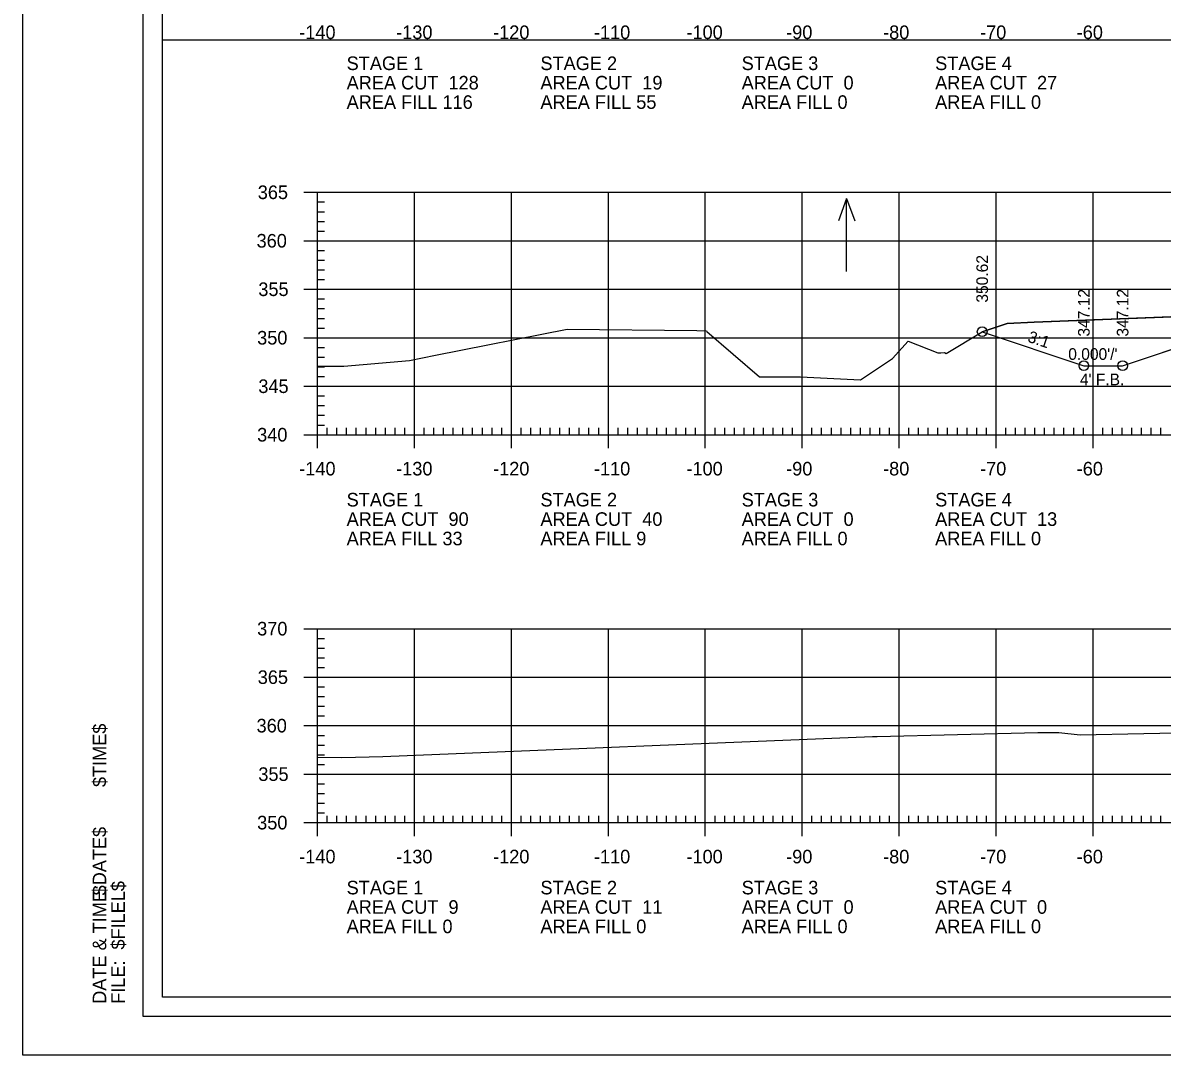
# Model space of a CAD drawing. Extents: x 1368910 to 1369601, y 380116 to 380950.
# Drawn here: x 1369267.2 to 1369384.7, y 380310.4 to 380416.9 of the extents above; entities that cross this region are included whole.
import ezdxf

# ---------------------------------------------------------------- set-up
doc = ezdxf.new("R2010")
doc.units = 0
for name, color, linetype in [('_STAGE 1 CUT', 7, 'Continuous'), ('R_Axis', 7, 'Continuous'), ('R_Axis Annot', 7, 'Continuous'), ('R_Border', 7, 'Continuous'), ('R_Border Notes', 7, 'Continuous'), ('R_Exist Surface', 7, 'Continuous'), ('R_Fin Surface', 7, 'Continuous'), ('R_Grid', 7, 'Continuous'), ('R_No Plot', 7, 'Continuous'), ('R_Water Annot', 7, 'Continuous'), ('R_Xsect Elev', 7, 'Continuous'), ('R_Xsect Slope', 7, 'Continuous')]:
    doc.layers.add(name, color=color, linetype=linetype)

msp = doc.modelspace()

# ---------------------------------------------------------------- linework, layer by layer
at = {"layer": '_STAGE 1 CUT'}
msp.add_line((1369366.16, 380385.04), (1369376.64, 380381.54), dxfattribs=at)
for points in [[(1369397.06, 380387.02), (1369371.53, 380386.03), (1369368.73, 380385.9), (1369366.16, 380385.04)], [(1369376.64, 380381.54), (1369380.64, 380381.54), (1369397.06, 380387.02)], [(1369366.16, 380385.04), (1369366.16, 380385.04)]]:
    msp.add_lwpolyline(points, dxfattribs=at)
at = {"layer": 'R_Axis'}
for p, q in [((1369296.19, 380399.42), (1369298.99, 380399.42)), ((1369297.59, 380374.42), (1369297.59, 380399.42)), ((1369297.59, 380398.42), (1369298.29, 380398.42)), ((1369297.59, 380397.42), (1369298.29, 380397.42)), ((1369297.59, 380396.42), (1369298.29, 380396.42)), ((1369297.59, 380395.42), (1369298.29, 380395.42)), ((1369296.19, 380394.42), (1369298.99, 380394.42)), ((1369297.59, 380393.42), (1369298.29, 380393.42)), ((1369297.59, 380392.42), (1369298.29, 380392.42)), ((1369297.59, 380391.42), (1369298.29, 380391.42)), ((1369297.59, 380390.42), (1369298.29, 380390.42)), ((1369296.19, 380389.42), (1369298.99, 380389.42)), ((1369297.59, 380388.42), (1369298.29, 380388.42)), ((1369297.59, 380387.42), (1369298.29, 380387.42)), ((1369297.59, 380386.42), (1369298.29, 380386.42)), ((1369297.59, 380385.42), (1369298.29, 380385.42)), ((1369296.19, 380384.42), (1369298.99, 380384.42)), ((1369297.59, 380383.42), (1369298.29, 380383.42)), ((1369297.59, 380382.42), (1369298.29, 380382.42)), ((1369297.59, 380381.42), (1369298.29, 380381.42)), ((1369297.59, 380380.42), (1369298.29, 380380.42)), ((1369296.19, 380379.42), (1369298.99, 380379.42)), ((1369297.59, 380378.42), (1369298.29, 380378.42)), ((1369297.59, 380377.42), (1369298.29, 380377.42)), ((1369297.59, 380376.42), (1369298.29, 380376.42)), ((1369297.59, 380373.02), (1369297.59, 380375.82)), ((1369307.59, 380373.02), (1369307.59, 380375.82)), ((1369317.59, 380373.02), (1369317.59, 380375.82)), ((1369327.59, 380373.02), (1369327.59, 380375.82)), ((1369337.59, 380373.02), (1369337.59, 380375.82)), ((1369347.59, 380373.02), (1369347.59, 380375.82)), ((1369357.59, 380373.02), (1369357.59, 380375.82)), ((1369367.59, 380373.02), (1369367.59, 380375.82)), ((1369377.59, 380373.02), (1369377.59, 380375.82)), ((1369297.59, 380375.42), (1369298.29, 380375.42)), ((1369298.59, 380374.42), (1369298.59, 380375.12)), ((1369299.59, 380374.42), (1369299.59, 380375.12)), ((1369300.59, 380374.42), (1369300.59, 380375.12)), ((1369301.59, 380374.42), (1369301.59, 380375.12)), ((1369302.59, 380374.42), (1369302.59, 380375.12)), ((1369303.59, 380374.42), (1369303.59, 380375.12)), ((1369304.59, 380374.42), (1369304.59, 380375.12)), ((1369305.59, 380374.42), (1369305.59, 380375.12)), ((1369306.59, 380374.42), (1369306.59, 380375.12)), ((1369308.59, 380374.42), (1369308.59, 380375.12)), ((1369309.59, 380374.42), (1369309.59, 380375.12)), ((1369310.59, 380374.42), (1369310.59, 380375.12)), ((1369311.59, 380374.42), (1369311.59, 380375.12)), ((1369312.59, 380374.42), (1369312.59, 380375.12)), ((1369313.59, 380374.42), (1369313.59, 380375.12)), ((1369314.59, 380374.42), (1369314.59, 380375.12)), ((1369315.59, 380374.42), (1369315.59, 380375.12)), ((1369316.59, 380374.42), (1369316.59, 380375.12)), ((1369318.59, 380374.42), (1369318.59, 380375.12)), ((1369319.59, 380374.42), (1369319.59, 380375.12)), ((1369320.59, 380374.42), (1369320.59, 380375.12)), ((1369321.59, 380374.42), (1369321.59, 380375.12)), ((1369322.59, 380374.42), (1369322.59, 380375.12)), ((1369323.59, 380374.42), (1369323.59, 380375.12)), ((1369324.59, 380374.42), (1369324.59, 380375.12)), ((1369325.59, 380374.42), (1369325.59, 380375.12)), ((1369326.59, 380374.42), (1369326.59, 380375.12)), ((1369328.59, 380374.42), (1369328.59, 380375.12)), ((1369329.59, 380374.42), (1369329.59, 380375.12)), ((1369330.59, 380374.42), (1369330.59, 380375.12)), ((1369331.59, 380374.42), (1369331.59, 380375.12)), ((1369332.59, 380374.42), (1369332.59, 380375.12)), ((1369333.59, 380374.42), (1369333.59, 380375.12)), ((1369334.59, 380374.42), (1369334.59, 380375.12)), ((1369335.59, 380374.42), (1369335.59, 380375.12)), ((1369336.59, 380374.42), (1369336.59, 380375.12)), ((1369338.59, 380374.42), (1369338.59, 380375.12)), ((1369339.59, 380374.42), (1369339.59, 380375.12)), ((1369340.59, 380374.42), (1369340.59, 380375.12)), ((1369341.59, 380374.42), (1369341.59, 380375.12)), ((1369342.59, 380374.42), (1369342.59, 380375.12)), ((1369343.59, 380374.42), (1369343.59, 380375.12)), ((1369344.59, 380374.42), (1369344.59, 380375.12)), ((1369345.59, 380374.42), (1369345.59, 380375.12)), ((1369346.59, 380374.42), (1369346.59, 380375.12)), ((1369348.59, 380374.42), (1369348.59, 380375.12)), ((1369349.59, 380374.42), (1369349.59, 380375.12)), ((1369350.59, 380374.42), (1369350.59, 380375.12)), ((1369351.59, 380374.42), (1369351.59, 380375.12)), ((1369352.59, 380374.42), (1369352.59, 380375.12)), ((1369353.59, 380374.42), (1369353.59, 380375.12)), ((1369354.59, 380374.42), (1369354.59, 380375.12)), ((1369355.59, 380374.42), (1369355.59, 380375.12)), ((1369356.59, 380374.42), (1369356.59, 380375.12)), ((1369358.59, 380374.42), (1369358.59, 380375.12)), ((1369359.59, 380374.42), (1369359.59, 380375.12)), ((1369360.59, 380374.42), (1369360.59, 380375.12)), ((1369361.59, 380374.42), (1369361.59, 380375.12)), ((1369362.59, 380374.42), (1369362.59, 380375.12)), ((1369363.59, 380374.42), (1369363.59, 380375.12)), ((1369364.59, 380374.42), (1369364.59, 380375.12)), ((1369365.59, 380374.42), (1369365.59, 380375.12)), ((1369366.59, 380374.42), (1369366.59, 380375.12)), ((1369368.59, 380374.42), (1369368.59, 380375.12)), ((1369369.59, 380374.42), (1369369.59, 380375.12)), ((1369370.59, 380374.42), (1369370.59, 380375.12)), ((1369371.59, 380374.42), (1369371.59, 380375.12)), ((1369372.59, 380374.42), (1369372.59, 380375.12)), ((1369373.59, 380374.42), (1369373.59, 380375.12)), ((1369374.59, 380374.42), (1369374.59, 380375.12)), ((1369375.59, 380374.42), (1369375.59, 380375.12)), ((1369376.59, 380374.42), (1369376.59, 380375.12)), ((1369378.59, 380374.42), (1369378.59, 380375.12)), ((1369379.59, 380374.42), (1369379.59, 380375.12)), ((1369380.59, 380374.42), (1369380.59, 380375.12)), ((1369381.59, 380374.42), (1369381.59, 380375.12)), ((1369382.59, 380374.42), (1369382.59, 380375.12)), ((1369383.59, 380374.42), (1369383.59, 380375.12)), ((1369384.59, 380374.42), (1369384.59, 380375.12)), ((1369296.19, 380374.42), (1369298.99, 380374.42)), ((1369297.59, 380374.42), (1369577.59, 380374.42)), ((1369296.19, 380354.42), (1369298.99, 380354.42)), ((1369297.59, 380334.42), (1369297.59, 380354.42)), ((1369297.59, 380353.42), (1369298.29, 380353.42)), ((1369297.59, 380352.42), (1369298.29, 380352.42)), ((1369297.59, 380351.42), (1369298.29, 380351.42)), ((1369297.59, 380350.42), (1369298.29, 380350.42)), ((1369296.19, 380349.42), (1369298.99, 380349.42)), ((1369297.59, 380348.42), (1369298.29, 380348.42)), ((1369297.59, 380347.42), (1369298.29, 380347.42)), ((1369297.59, 380346.42), (1369298.29, 380346.42)), ((1369297.59, 380345.42), (1369298.29, 380345.42)), ((1369296.19, 380344.42), (1369298.99, 380344.42)), ((1369297.59, 380343.42), (1369298.29, 380343.42)), ((1369297.59, 380342.42), (1369298.29, 380342.42)), ((1369297.59, 380341.42), (1369298.29, 380341.42)), ((1369297.59, 380340.42), (1369298.29, 380340.42)), ((1369296.19, 380339.42), (1369298.99, 380339.42)), ((1369297.59, 380338.42), (1369298.29, 380338.42)), ((1369297.59, 380337.42), (1369298.29, 380337.42)), ((1369297.59, 380336.42), (1369298.29, 380336.42)), ((1369297.59, 380333.02), (1369297.59, 380335.82)), ((1369307.59, 380333.02), (1369307.59, 380335.82)), ((1369317.59, 380333.02), (1369317.59, 380335.82)), ((1369327.59, 380333.02), (1369327.59, 380335.82)), ((1369337.59, 380333.02), (1369337.59, 380335.82)), ((1369347.59, 380333.02), (1369347.59, 380335.82)), ((1369357.59, 380333.02), (1369357.59, 380335.82)), ((1369367.59, 380333.02), (1369367.59, 380335.82)), ((1369377.59, 380333.02), (1369377.59, 380335.82)), ((1369297.59, 380335.42), (1369298.29, 380335.42)), ((1369298.59, 380334.42), (1369298.59, 380335.12)), ((1369299.59, 380334.42), (1369299.59, 380335.12)), ((1369300.59, 380334.42), (1369300.59, 380335.12)), ((1369301.59, 380334.42), (1369301.59, 380335.12)), ((1369302.59, 380334.42), (1369302.59, 380335.12)), ((1369303.59, 380334.42), (1369303.59, 380335.12)), ((1369304.59, 380334.42), (1369304.59, 380335.12)), ((1369305.59, 380334.42), (1369305.59, 380335.12)), ((1369306.59, 380334.42), (1369306.59, 380335.12)), ((1369308.59, 380334.42), (1369308.59, 380335.12)), ((1369309.59, 380334.42), (1369309.59, 380335.12)), ((1369310.59, 380334.42), (1369310.59, 380335.12)), ((1369311.59, 380334.42), (1369311.59, 380335.12)), ((1369312.59, 380334.42), (1369312.59, 380335.12)), ((1369313.59, 380334.42), (1369313.59, 380335.12)), ((1369314.59, 380334.42), (1369314.59, 380335.12)), ((1369315.59, 380334.42), (1369315.59, 380335.12)), ((1369316.59, 380334.42), (1369316.59, 380335.12)), ((1369318.59, 380334.42), (1369318.59, 380335.12)), ((1369319.59, 380334.42), (1369319.59, 380335.12)), ((1369320.59, 380334.42), (1369320.59, 380335.12)), ((1369321.59, 380334.42), (1369321.59, 380335.12)), ((1369322.59, 380334.42), (1369322.59, 380335.12)), ((1369323.59, 380334.42), (1369323.59, 380335.12)), ((1369324.59, 380334.42), (1369324.59, 380335.12)), ((1369325.59, 380334.42), (1369325.59, 380335.12)), ((1369326.59, 380334.42), (1369326.59, 380335.12)), ((1369328.59, 380334.42), (1369328.59, 380335.12)), ((1369329.59, 380334.42), (1369329.59, 380335.12)), ((1369330.59, 380334.42), (1369330.59, 380335.12)), ((1369331.59, 380334.42), (1369331.59, 380335.12)), ((1369332.59, 380334.42), (1369332.59, 380335.12)), ((1369333.59, 380334.42), (1369333.59, 380335.12)), ((1369334.59, 380334.42), (1369334.59, 380335.12)), ((1369335.59, 380334.42), (1369335.59, 380335.12)), ((1369336.59, 380334.42), (1369336.59, 380335.12)), ((1369338.59, 380334.42), (1369338.59, 380335.12)), ((1369339.59, 380334.42), (1369339.59, 380335.12)), ((1369340.59, 380334.42), (1369340.59, 380335.12)), ((1369341.59, 380334.42), (1369341.59, 380335.12)), ((1369342.59, 380334.42), (1369342.59, 380335.12)), ((1369343.59, 380334.42), (1369343.59, 380335.12)), ((1369344.59, 380334.42), (1369344.59, 380335.12)), ((1369345.59, 380334.42), (1369345.59, 380335.12)), ((1369346.59, 380334.42), (1369346.59, 380335.12)), ((1369348.59, 380334.42), (1369348.59, 380335.12)), ((1369349.59, 380334.42), (1369349.59, 380335.12)), ((1369350.59, 380334.42), (1369350.59, 380335.12)), ((1369351.59, 380334.42), (1369351.59, 380335.12)), ((1369352.59, 380334.42), (1369352.59, 380335.12)), ((1369353.59, 380334.42), (1369353.59, 380335.12)), ((1369354.59, 380334.42), (1369354.59, 380335.12)), ((1369355.59, 380334.42), (1369355.59, 380335.12)), ((1369356.59, 380334.42), (1369356.59, 380335.12)), ((1369358.59, 380334.42), (1369358.59, 380335.12)), ((1369359.59, 380334.42), (1369359.59, 380335.12)), ((1369360.59, 380334.42), (1369360.59, 380335.12)), ((1369361.59, 380334.42), (1369361.59, 380335.12)), ((1369362.59, 380334.42), (1369362.59, 380335.12)), ((1369363.59, 380334.42), (1369363.59, 380335.12)), ((1369364.59, 380334.42), (1369364.59, 380335.12)), ((1369365.59, 380334.42), (1369365.59, 380335.12)), ((1369366.59, 380334.42), (1369366.59, 380335.12)), ((1369368.59, 380334.42), (1369368.59, 380335.12)), ((1369369.59, 380334.42), (1369369.59, 380335.12)), ((1369370.59, 380334.42), (1369370.59, 380335.12)), ((1369371.59, 380334.42), (1369371.59, 380335.12)), ((1369372.59, 380334.42), (1369372.59, 380335.12)), ((1369373.59, 380334.42), (1369373.59, 380335.12)), ((1369374.59, 380334.42), (1369374.59, 380335.12)), ((1369375.59, 380334.42), (1369375.59, 380335.12)), ((1369376.59, 380334.42), (1369376.59, 380335.12)), ((1369378.59, 380334.42), (1369378.59, 380335.12)), ((1369379.59, 380334.42), (1369379.59, 380335.12)), ((1369380.59, 380334.42), (1369380.59, 380335.12)), ((1369381.59, 380334.42), (1369381.59, 380335.12)), ((1369382.59, 380334.42), (1369382.59, 380335.12)), ((1369383.59, 380334.42), (1369383.59, 380335.12)), ((1369384.59, 380334.42), (1369384.59, 380335.12)), ((1369296.19, 380334.42), (1369298.99, 380334.42)), ((1369297.59, 380334.42), (1369577.59, 380334.42))]:
    msp.add_line(p, q, dxfattribs=at)
at = {"layer": 'R_Border'}
for p, q in [((1369279.59, 380314.42), (1369279.59, 380519.88)), ((1369279.59, 380314.42), (1369279.59, 380314.42)), ((1369595.77, 380314.42), (1369279.59, 380314.42))]:
    msp.add_line(p, q, dxfattribs=at)
at = {"layer": 'R_Exist Surface'}
for points in [[(1369297.59, 380381.5), (1369300.31, 380381.49), (1369307.07, 380382.09), (1369309.76, 380382.63), (1369323.33, 380385.31), (1369336.72, 380385.15), (1369337.72, 380385.14), (1369337.76, 380385.08), (1369343.17, 380380.4), (1369347.4, 380380.38), (1369353.59, 380380.09), (1369356.9, 380382.27), (1369358.52, 380384.05), (1369361.58, 380382.87), (1369361.87, 380382.86), (1369362.27, 380382.89), (1369362.45, 380382.81), (1369366.16, 380385.04), (1369368.73, 380385.9), (1369371.53, 380386.03), (1369397.24, 380387.02)], [(1369297.59, 380341.16), (1369300.09, 380341.12), (1369304.33, 380341.25), (1369354.84, 380343.3), (1369355.32, 380343.31), (1369371.88, 380343.7), (1369374.05, 380343.72), (1369376.27, 380343.48), (1369389.41, 380343.75)]]:
    msp.add_lwpolyline(points, dxfattribs=at)
at = {"layer": 'R_Fin Surface'}
msp.add_lwpolyline([(1369366.15, 380385.04), (1369376.64, 380381.54), (1369380.64, 380381.54), (1369404.59, 380389.53), (1369412.86, 380390.9), (1369418.59, 380391.86), (1369426.59, 380392.18), (1369437.59, 380392.4), (1369448.59, 380392.18), (1369456.59, 380391.86), (1369462.32, 380390.9), (1369470.59, 380389.53), (1369478.65, 380386.84), (1369482.65, 380386.84), (1369492.02, 380389.96)], dxfattribs=at)
at = {"layer": 'R_Grid'}
for p, q in [((1369297.59, 380399.42), (1369577.59, 380399.42)), ((1369297.59, 380374.42), (1369297.59, 380399.42)), ((1369307.59, 380374.42), (1369307.59, 380399.42)), ((1369317.59, 380374.42), (1369317.59, 380399.42)), ((1369327.59, 380374.42), (1369327.59, 380399.42)), ((1369337.59, 380374.42), (1369337.59, 380399.42)), ((1369347.59, 380374.42), (1369347.59, 380399.42)), ((1369357.59, 380374.42), (1369357.59, 380399.42)), ((1369367.59, 380374.42), (1369367.59, 380399.42)), ((1369377.59, 380374.42), (1369377.59, 380399.42)), ((1369297.59, 380394.42), (1369577.59, 380394.42)), ((1369297.59, 380389.42), (1369577.59, 380389.42)), ((1369297.59, 380384.42), (1369577.59, 380384.42)), ((1369297.59, 380379.42), (1369577.59, 380379.42)), ((1369297.59, 380374.42), (1369577.59, 380374.42)), ((1369297.59, 380354.42), (1369577.59, 380354.42)), ((1369297.59, 380334.42), (1369297.59, 380354.42)), ((1369307.59, 380334.42), (1369307.59, 380354.42)), ((1369317.59, 380334.42), (1369317.59, 380354.42)), ((1369327.59, 380334.42), (1369327.59, 380354.42)), ((1369337.59, 380334.42), (1369337.59, 380354.42)), ((1369347.59, 380334.42), (1369347.59, 380354.42)), ((1369357.59, 380334.42), (1369357.59, 380354.42)), ((1369367.59, 380334.42), (1369367.59, 380354.42)), ((1369377.59, 380334.42), (1369377.59, 380354.42)), ((1369297.59, 380349.42), (1369577.59, 380349.42)), ((1369297.59, 380344.42), (1369577.59, 380344.42)), ((1369297.59, 380339.42), (1369577.59, 380339.42)), ((1369297.59, 380334.42), (1369577.59, 380334.42))]:
    msp.add_line(p, q, dxfattribs=at)
at = {"layer": 'R_No Plot'}
for points in [[(1369267.18, 380523.78), (1369600.52, 380523.78), (1369600.52, 380310.44), (1369267.18, 380310.44)], [(1369281.59, 380517.88), (1369531.13, 380517.88), (1369531.13, 380508), (1369548.67, 380508), (1369572.77, 380508), (1369572.77, 380485.67), (1369593.77, 380485.67), (1369593.77, 380316.42), (1369281.59, 380316.42)], [(1369281.59, 380415.15), (1369593.77, 380415.15), (1369593.77, 380316.42), (1369281.59, 380316.42)]]:
    msp.add_lwpolyline(points, close=True, dxfattribs=at)
for centre in [(1369366.15, 380385.04), (1369376.64, 380381.54), (1369380.64, 380381.54)]:
    msp.add_circle(centre, 0.5, dxfattribs=at)
at = {"layer": 'R_Water Annot'}
for p, q in [((1369352.16, 380398.79), (1369351.32, 380396.48)), ((1369352.16, 380391.25), (1369352.16, 380398.79)), ((1369352.16, 380398.79), (1369353, 380396.48))]:
    msp.add_line(p, q, dxfattribs=at)

# ---------------------------------------------------------------- texts
at = {"layer": 'R_Axis Annot'}
for s, p in [('-140', (1369295.7, 380415.22)), ('-130', (1369305.7, 380415.22)), ('-120', (1369315.7, 380415.22)), ('-110', (1369326.1, 380415.22)), ('-100', (1369335.64, 380415.22)), ('-90', (1369345.93, 380415.22)), ('-80', (1369355.93, 380415.22)), ('-70', (1369365.93, 380415.22)), ('-60', (1369375.9, 380415.22)), ('STAGE 1', (1369300.59, 380412.02)), ('STAGE 2', (1369320.58, 380412.02)), ('STAGE 3', (1369341.34, 380412.02)), ('STAGE 4', (1369361.3, 380412.02)), ('AREA CUT  128', (1369300.59, 380410.02)), ('AREA CUT  19', (1369320.58, 380410.02)), ('AREA CUT  0', (1369341.34, 380410.02)), ('AREA CUT  27', (1369361.3, 380410.02)), ('AREA FILL 116', (1369300.59, 380408.02)), ('AREA FILL 55', (1369320.58, 380408.02)), ('AREA FILL 0', (1369341.34, 380408.02)), ('AREA FILL 0', (1369361.3, 380408.02)), ('365', (1369291.42, 380398.72)), ('360', (1369291.3, 380393.72)), ('355', (1369291.48, 380388.72)), ('350', (1369291.36, 380383.72)), ('345', (1369291.48, 380378.72)), ('340', (1369291.36, 380373.72)), ('-140', (1369295.7, 380370.22)), ('-130', (1369305.7, 380370.22)), ('-120', (1369315.7, 380370.22)), ('-110', (1369326.1, 380370.22)), ('-100', (1369335.64, 380370.22)), ('-90', (1369345.93, 380370.22)), ('-80', (1369355.93, 380370.22)), ('-70', (1369365.93, 380370.22)), ('-60', (1369375.9, 380370.22)), ('STAGE 1', (1369300.59, 380367.02)), ('STAGE 2', (1369320.58, 380367.02)), ('STAGE 3', (1369341.34, 380367.02)), ('STAGE 4', (1369361.3, 380367.02)), ('AREA CUT  90', (1369300.59, 380365.02)), ('AREA CUT  40', (1369320.58, 380365.02)), ('AREA CUT  0', (1369341.34, 380365.02)), ('AREA CUT  13', (1369361.3, 380365.02)), ('AREA FILL 33', (1369300.59, 380363.02)), ('AREA FILL 9', (1369320.58, 380363.02)), ('AREA FILL 0', (1369341.34, 380363.02)), ('AREA FILL 0', (1369361.3, 380363.02)), ('370', (1369291.36, 380353.72)), ('365', (1369291.42, 380348.72)), ('360', (1369291.3, 380343.72)), ('355', (1369291.48, 380338.72)), ('350', (1369291.36, 380333.72)), ('-140', (1369295.7, 380330.22)), ('-130', (1369305.7, 380330.22)), ('-120', (1369315.7, 380330.22)), ('-110', (1369326.1, 380330.22)), ('-100', (1369335.64, 380330.22)), ('-90', (1369345.93, 380330.22)), ('-80', (1369355.93, 380330.22)), ('-70', (1369365.93, 380330.22)), ('-60', (1369375.9, 380330.22)), ('STAGE 1', (1369300.59, 380327.02)), ('STAGE 2', (1369320.58, 380327.02)), ('STAGE 3', (1369341.34, 380327.02)), ('STAGE 4', (1369361.3, 380327.02)), ('AREA CUT  9', (1369300.59, 380325.02)), ('AREA CUT  11', (1369320.58, 380325.02)), ('AREA CUT  0', (1369341.34, 380325.02)), ('AREA CUT  0', (1369361.3, 380325.02)), ('AREA FILL 0', (1369300.59, 380323.02)), ('AREA FILL 0', (1369320.58, 380323.02)), ('AREA FILL 0', (1369341.34, 380323.02)), ('AREA FILL 0', (1369361.3, 380323.02))]:
    msp.add_text(s, height=1.4, dxfattribs=at).set_placement(p)
at = {"layer": 'R_Border Notes'}
for s, height, p in [('$TIME$', 1.397, (1369275.79, 380338.09)), ('$DATE$', 1.397, (1369275.79, 380326.92)), ('DATE & TIME:', 1.3968, (1369275.79, 380315.74)), ('$FILEL$', 1.397, (1369277.71, 380321.33)), ('FILE: ', 1.397, (1369277.71, 380315.74))]:
    msp.add_text(s, height=height, rotation=90, dxfattribs=at).set_placement(p)
at = {"layer": 'R_Xsect Elev'}
for s, p in [('350.62', (1369366.75, 380388.04)), ('347.12', (1369377.24, 380384.54)), ('347.12', (1369381.24, 380384.54))]:
    msp.add_text(s, height=1.2, rotation=90, dxfattribs=at).set_placement(p)
at = {"layer": 'R_Xsect Slope'}
for s, rotation, p in [('3:1', 341.5651, (1369370.76, 380384.03)), ("0.000'/'", 360, (1369375.03, 380382.14)), ("4' F.B.", 360, (1369376.23, 380379.52)), ("4' F.B.", 360, (1369376.23, 380379.52))]:
    msp.add_text(s, height=1.2, rotation=rotation, dxfattribs=at).set_placement(p)

doc.saveas('drawing.dxf')
